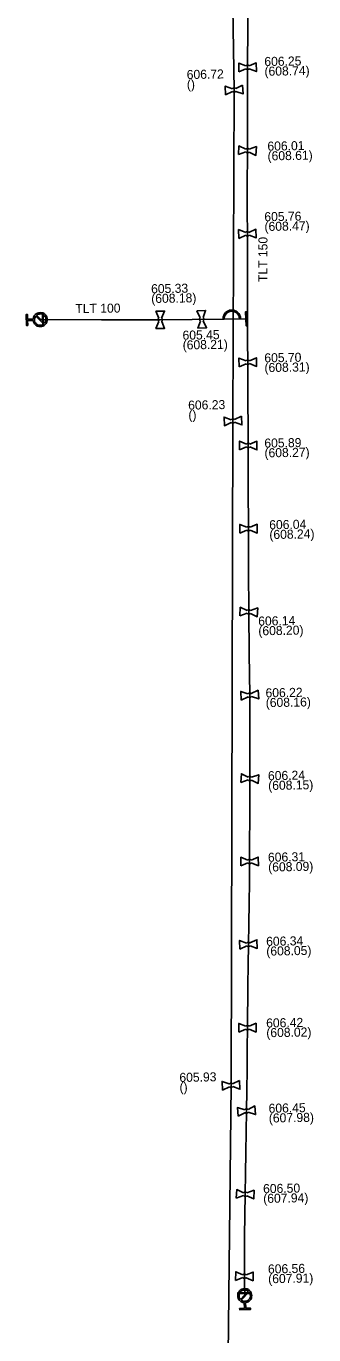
# Model space of a CAD drawing. Extents: x -643842 to -636370, y -1119190 to -1110210.
# Drawn here: x -640525.1 to -640483.8, y -1115566.2 to -1115378.3 of the extents above; entities that cross this region are included whole.
import ezdxf

# ---------------------------------------------------------------- set-up
doc = ezdxf.new("R2010")
doc.units = 0
for name, color, linetype in [('9', 7, 'Continuous'), ('Default', 7, 'Continuous'), ('Level 16', 7, 'Continuous'), ('Level 20', 7, 'Continuous'), ('Level 21', 7, 'Continuous'), ('Level 27', 7, 'Continuous'), ('Level 28', 7, 'Continuous'), ('Level 33', 7, 'Continuous')]:
    doc.layers.add(name, color=color, linetype=linetype)

msp = doc.modelspace()

# ---------------------------------------------------------------- linework, layer by layer
at = {"layer": '9'}
for points in [[(-640496.7, -1115420.35), (-640496.85, -1115420.35)], [(-640494.35, -1115420.35), (-640494.51, -1115420.35)]]:
    msp.add_lwpolyline(points, dxfattribs=at)
at = {"layer": 'Default'}
for points in [[(-640493.57, -1115384.05), (-640493.54, -1115384.01), (-640493.49, -1115383.98), (-640493.42, -1115383.94), (-640493.33, -1115383.94), (-640493.25, -1115383.94), (-640493.18, -1115383.98), (-640493.13, -1115384), (-640493.1, -1115384.04)], [(-640493.09, -1115384.45), (-640493.12, -1115384.49), (-640493.17, -1115384.52), (-640493.24, -1115384.56), (-640493.33, -1115384.56), (-640493.41, -1115384.56), (-640493.48, -1115384.52), (-640493.53, -1115384.5), (-640493.57, -1115384.46)], [(-640495.52, -1115387.32), (-640495.49, -1115387.28), (-640495.44, -1115387.25), (-640495.37, -1115387.2), (-640495.29, -1115387.2), (-640495.2, -1115387.19), (-640495.13, -1115387.23), (-640495.08, -1115387.26), (-640495.04, -1115387.29)], [(-640495.02, -1115387.7), (-640495.05, -1115387.74), (-640495.1, -1115387.77), (-640495.17, -1115387.82), (-640495.25, -1115387.82), (-640495.34, -1115387.83), (-640495.41, -1115387.79), (-640495.46, -1115387.76), (-640495.5, -1115387.73)], [(-640493.12, -1115396.42), (-640493.16, -1115396.46), (-640493.21, -1115396.49), (-640493.28, -1115396.53), (-640493.36, -1115396.52), (-640493.45, -1115396.52), (-640493.52, -1115396.47), (-640493.56, -1115396.44), (-640493.6, -1115396.4)], [(-640493.58, -1115395.99), (-640493.54, -1115395.96), (-640493.49, -1115395.93), (-640493.42, -1115395.89), (-640493.34, -1115395.9), (-640493.25, -1115395.9), (-640493.18, -1115395.95), (-640493.14, -1115395.98), (-640493.1, -1115396.02)], [(-640493.61, -1115407.95), (-640493.58, -1115407.91), (-640493.53, -1115407.88), (-640493.46, -1115407.84), (-640493.38, -1115407.84), (-640493.29, -1115407.84), (-640493.22, -1115407.88), (-640493.17, -1115407.9), (-640493.14, -1115407.94)], [(-640493.13, -1115408.35), (-640493.16, -1115408.39), (-640493.21, -1115408.42), (-640493.28, -1115408.46), (-640493.36, -1115408.46), (-640493.45, -1115408.46), (-640493.52, -1115408.42), (-640493.57, -1115408.4), (-640493.6, -1115408.36)], [(-640524.09, -1115420.4), (-640524.07, -1115420.04), (-640523.81, -1115419.77), (-640523.52, -1115419.48), (-640523.11, -1115419.47), (-640522.69, -1115419.46), (-640522.4, -1115419.75), (-640522.1, -1115420.04), (-640522.09, -1115420.45), (-640522.08, -1115420.87), (-640522.37, -1115421.16), (-640522.66, -1115421.46), (-640523.07, -1115421.47), (-640523.49, -1115421.48), (-640523.78, -1115421.19), (-640524.05, -1115420.94), (-640524.08, -1115420.58)], [(-640523.74, -1115419.97), (-640523.91, -1115420.19), (-640523.9, -1115420.49), (-640523.9, -1115420.83), (-640523.66, -1115421.06), (-640523.41, -1115421.29), (-640523.08, -1115421.28), (-640522.78, -1115421.28), (-640522.57, -1115421.1)], [(-640522.44, -1115420.97), (-640522.27, -1115420.75), (-640522.28, -1115420.46), (-640522.29, -1115420.12), (-640522.53, -1115419.89), (-640522.77, -1115419.65), (-640523.11, -1115419.66), (-640523.4, -1115419.67), (-640523.61, -1115419.84)], [(-640496.85, -1115420.35), (-640496.85, -1115420.03), (-640496.69, -1115419.73), (-640496.52, -1115419.43), (-640496.22, -1115419.26), (-640495.92, -1115419.1), (-640495.6, -1115419.1), (-640495.29, -1115419.1), (-640494.99, -1115419.26), (-640494.69, -1115419.43), (-640494.52, -1115419.73), (-640494.35, -1115420.03), (-640494.35, -1115420.35)], [(-640494.51, -1115420.35), (-640494.51, -1115420.07), (-640494.66, -1115419.8), (-640494.81, -1115419.54), (-640495.07, -1115419.4), (-640495.33, -1115419.26), (-640495.6, -1115419.26), (-640495.88, -1115419.26), (-640496.14, -1115419.4), (-640496.4, -1115419.54), (-640496.55, -1115419.8), (-640496.7, -1115420.07), (-640496.7, -1115420.35)], [(-640506.07, -1115420.73), (-640506.11, -1115420.69), (-640506.14, -1115420.65), (-640506.18, -1115420.57), (-640506.18, -1115420.49), (-640506.18, -1115420.41), (-640506.14, -1115420.33), (-640506.12, -1115420.29), (-640506.08, -1115420.25)], [(-640505.67, -1115420.25), (-640505.63, -1115420.28), (-640505.6, -1115420.33), (-640505.56, -1115420.41), (-640505.56, -1115420.49), (-640505.56, -1115420.57), (-640505.6, -1115420.64), (-640505.62, -1115420.69), (-640505.66, -1115420.73)], [(-640500.11, -1115420.67), (-640500.15, -1115420.64), (-640500.18, -1115420.59), (-640500.23, -1115420.52), (-640500.23, -1115420.44), (-640500.24, -1115420.36), (-640500.2, -1115420.28), (-640500.18, -1115420.23), (-640500.14, -1115420.19)], [(-640499.73, -1115420.17), (-640499.69, -1115420.2), (-640499.66, -1115420.25), (-640499.61, -1115420.32), (-640499.61, -1115420.4), (-640499.6, -1115420.48), (-640499.64, -1115420.56), (-640499.66, -1115420.61), (-640499.7, -1115420.64)], [(-640493.55, -1115426.39), (-640493.52, -1115426.35), (-640493.47, -1115426.32), (-640493.4, -1115426.28), (-640493.32, -1115426.28), (-640493.24, -1115426.28), (-640493.16, -1115426.32), (-640493.11, -1115426.34), (-640493.08, -1115426.38)], [(-640493.07, -1115426.79), (-640493.1, -1115426.83), (-640493.15, -1115426.86), (-640493.22, -1115426.9), (-640493.3, -1115426.9), (-640493.38, -1115426.9), (-640493.46, -1115426.86), (-640493.51, -1115426.84), (-640493.54, -1115426.8)], [(-640495.69, -1115434.83), (-640495.66, -1115434.79), (-640495.61, -1115434.76), (-640495.54, -1115434.71), (-640495.46, -1115434.71), (-640495.37, -1115434.7), (-640495.3, -1115434.74), (-640495.25, -1115434.77), (-640495.21, -1115434.8)], [(-640495.19, -1115435.21), (-640495.22, -1115435.25), (-640495.27, -1115435.28), (-640495.34, -1115435.33), (-640495.42, -1115435.33), (-640495.51, -1115435.34), (-640495.58, -1115435.3), (-640495.63, -1115435.27), (-640495.67, -1115435.24)], [(-640493.48, -1115438.33), (-640493.44, -1115438.3), (-640493.4, -1115438.27), (-640493.32, -1115438.23), (-640493.24, -1115438.23), (-640493.16, -1115438.23), (-640493.08, -1115438.27), (-640493.04, -1115438.3), (-640493, -1115438.34)], [(-640493, -1115438.74), (-640493.04, -1115438.78), (-640493.09, -1115438.81), (-640493.16, -1115438.85), (-640493.24, -1115438.85), (-640493.32, -1115438.85), (-640493.4, -1115438.81), (-640493.44, -1115438.78), (-640493.48, -1115438.74)], [(-640493.45, -1115450.28), (-640493.41, -1115450.24), (-640493.37, -1115450.21), (-640493.29, -1115450.17), (-640493.21, -1115450.17), (-640493.13, -1115450.17), (-640493.06, -1115450.21), (-640493.01, -1115450.24), (-640492.97, -1115450.28)], [(-640492.97, -1115450.68), (-640493.01, -1115450.72), (-640493.05, -1115450.75), (-640493.13, -1115450.79), (-640493.21, -1115450.79), (-640493.29, -1115450.79), (-640493.37, -1115450.75), (-640493.41, -1115450.72), (-640493.45, -1115450.68)], [(-640492.93, -1115462.64), (-640492.97, -1115462.68), (-640493.02, -1115462.71), (-640493.09, -1115462.75), (-640493.17, -1115462.74), (-640493.26, -1115462.74), (-640493.33, -1115462.69), (-640493.37, -1115462.66), (-640493.41, -1115462.62)], [(-640493.39, -1115462.21), (-640493.35, -1115462.18), (-640493.31, -1115462.15), (-640493.23, -1115462.11), (-640493.15, -1115462.12), (-640493.06, -1115462.12), (-640492.99, -1115462.17), (-640492.95, -1115462.2), (-640492.91, -1115462.24)], [(-640493.28, -1115474.19), (-640493.25, -1115474.15), (-640493.2, -1115474.12), (-640493.13, -1115474.07), (-640493.05, -1115474.07), (-640492.97, -1115474.06), (-640492.89, -1115474.1), (-640492.84, -1115474.12), (-640492.81, -1115474.16)], [(-640492.78, -1115474.57), (-640492.81, -1115474.61), (-640492.86, -1115474.64), (-640492.93, -1115474.69), (-640493.01, -1115474.69), (-640493.09, -1115474.7), (-640493.17, -1115474.66), (-640493.22, -1115474.64), (-640493.25, -1115474.6)], [(-640492.79, -1115486.57), (-640492.83, -1115486.6), (-640492.88, -1115486.63), (-640492.96, -1115486.67), (-640493.04, -1115486.66), (-640493.12, -1115486.66), (-640493.19, -1115486.61), (-640493.24, -1115486.58), (-640493.27, -1115486.54)], [(-640493.25, -1115486.13), (-640493.21, -1115486.1), (-640493.16, -1115486.07), (-640493.08, -1115486.03), (-640493, -1115486.04), (-640492.92, -1115486.04), (-640492.85, -1115486.09), (-640492.8, -1115486.12), (-640492.77, -1115486.16)], [(-640493.29, -1115498.05), (-640493.26, -1115498.01), (-640493.21, -1115497.98), (-640493.14, -1115497.94), (-640493.05, -1115497.94), (-640492.97, -1115497.94), (-640492.9, -1115497.98), (-640492.85, -1115498), (-640492.82, -1115498.04)], [(-640492.81, -1115498.45), (-640492.84, -1115498.49), (-640492.89, -1115498.52), (-640492.96, -1115498.56), (-640493.05, -1115498.56), (-640493.13, -1115498.56), (-640493.2, -1115498.52), (-640493.25, -1115498.5), (-640493.29, -1115498.46)], [(-640493.47, -1115509.96), (-640493.43, -1115509.92), (-640493.39, -1115509.9), (-640493.31, -1115509.85), (-640493.23, -1115509.85), (-640493.15, -1115509.84), (-640493.08, -1115509.88), (-640493.03, -1115509.91), (-640492.99, -1115509.95)], [(-640492.98, -1115510.35), (-640493.01, -1115510.4), (-640493.05, -1115510.42), (-640493.13, -1115510.47), (-640493.21, -1115510.47), (-640493.29, -1115510.48), (-640493.37, -1115510.44), (-640493.41, -1115510.41), (-640493.45, -1115510.37)], [(-640493.6, -1115521.91), (-640493.57, -1115521.87), (-640493.52, -1115521.84), (-640493.44, -1115521.8), (-640493.36, -1115521.8), (-640493.28, -1115521.8), (-640493.21, -1115521.84), (-640493.16, -1115521.86), (-640493.12, -1115521.9)], [(-640493.12, -1115522.31), (-640493.16, -1115522.35), (-640493.2, -1115522.38), (-640493.28, -1115522.42), (-640493.36, -1115522.42), (-640493.44, -1115522.42), (-640493.52, -1115522.38), (-640493.56, -1115522.36), (-640493.6, -1115522.32)], [(-640495.96, -1115530.19), (-640495.93, -1115530.15), (-640495.88, -1115530.12), (-640495.81, -1115530.07), (-640495.73, -1115530.07), (-640495.64, -1115530.06), (-640495.57, -1115530.1), (-640495.52, -1115530.13), (-640495.48, -1115530.16)], [(-640495.46, -1115530.57), (-640495.49, -1115530.61), (-640495.54, -1115530.64), (-640495.61, -1115530.69), (-640495.69, -1115530.69), (-640495.78, -1115530.7), (-640495.85, -1115530.66), (-640495.9, -1115530.63), (-640495.94, -1115530.6)], [(-640493.75, -1115533.9), (-640493.72, -1115533.86), (-640493.67, -1115533.83), (-640493.6, -1115533.78), (-640493.52, -1115533.77), (-640493.44, -1115533.76), (-640493.36, -1115533.79), (-640493.31, -1115533.82), (-640493.27, -1115533.85)], [(-640493.23, -1115534.26), (-640493.26, -1115534.3), (-640493.31, -1115534.33), (-640493.38, -1115534.38), (-640493.46, -1115534.39), (-640493.54, -1115534.4), (-640493.62, -1115534.36), (-640493.67, -1115534.34), (-640493.71, -1115534.31)], [(-640493.91, -1115545.8), (-640493.87, -1115545.77), (-640493.83, -1115545.74), (-640493.75, -1115545.7), (-640493.67, -1115545.71), (-640493.58, -1115545.71), (-640493.51, -1115545.76), (-640493.47, -1115545.78), (-640493.43, -1115545.83)], [(-640493.45, -1115546.23), (-640493.49, -1115546.27), (-640493.54, -1115546.3), (-640493.61, -1115546.34), (-640493.69, -1115546.33), (-640493.78, -1115546.33), (-640493.85, -1115546.28), (-640493.89, -1115546.26), (-640493.93, -1115546.21)], [(-640493.56, -1115558), (-640493.59, -1115558.04), (-640493.64, -1115558.06), (-640493.71, -1115558.1), (-640493.8, -1115558.1), (-640493.88, -1115558.1), (-640493.95, -1115558.06), (-640494, -1115558.03), (-640494.03, -1115557.99)], [(-640494.02, -1115557.58), (-640493.99, -1115557.54), (-640493.94, -1115557.52), (-640493.87, -1115557.48), (-640493.78, -1115557.48), (-640493.7, -1115557.48), (-640493.63, -1115557.52), (-640493.58, -1115557.55), (-640493.55, -1115557.59)], [(-640493.81, -1115561.58), (-640494.17, -1115561.56), (-640494.44, -1115561.31), (-640494.74, -1115561.02), (-640494.75, -1115560.61), (-640494.76, -1115560.19), (-640494.48, -1115559.89), (-640494.19, -1115559.59), (-640493.78, -1115559.58), (-640493.36, -1115559.57), (-640493.06, -1115559.85), (-640492.76, -1115560.14), (-640492.75, -1115560.55), (-640492.74, -1115560.97), (-640493.02, -1115561.27), (-640493.27, -1115561.54), (-640493.63, -1115561.57)], [(-640493.26, -1115559.93), (-640493.48, -1115559.76), (-640493.77, -1115559.77), (-640494.11, -1115559.78), (-640494.34, -1115560.02), (-640494.57, -1115560.27), (-640494.56, -1115560.61), (-640494.55, -1115560.89), (-640494.37, -1115561.11)], [(-640494.24, -1115561.23), (-640494.02, -1115561.4), (-640493.72, -1115561.39), (-640493.39, -1115561.38), (-640493.16, -1115561.14), (-640492.93, -1115560.9), (-640492.94, -1115560.56), (-640492.94, -1115560.27), (-640493.13, -1115560.05)]]:
    msp.add_open_spline(points, degree=3, dxfattribs=at)
at = {"layer": 'Level 16'}
for points in [[(-640522.67, -1115419.72), (-640522.62, -1115421.22), (-640522.71, -1115421.22), (-640522.76, -1115419.72), (-640522.67, -1115419.72)], [(-640493.5, -1115419.35), (-640493.42, -1115421.35), (-640493.54, -1115421.35), (-640493.62, -1115419.35), (-640493.5, -1115419.35)], [(-640494.49, -1115560.19), (-640492.99, -1115560.17), (-640492.99, -1115560.27), (-640494.49, -1115560.29), (-640494.49, -1115560.19)]]:
    msp.add_lwpolyline(points, dxfattribs=at)
at = {"layer": 'Level 21'}
for points in [[(-640496.45, -1115599.22), (-640495.71, -1115530.38), (-640495.44, -1115435.02), (-640495.27, -1115387.51), (-640496.24, -1115328.66), (-640496.1, -1115321.04), (-640496.38, -1115277.05), (-640496.25, -1115224.64), (-640497.04, -1115169.68), (-640497.03, -1115117.29), (-640497.07, -1115108.05), (-640496.9, -1115096.11)], [(-640493.19, -1115367.24), (-640493.22, -1115369.77), (-640493.26, -1115372.29), (-640493.28, -1115375.27), (-640493.3, -1115378.26), (-640493.33, -1115384.25), (-640493.34, -1115390.24), (-640493.35, -1115396.21), (-640493.42, -1115401.65), (-640493.4, -1115404.9), (-640493.37, -1115408.15), (-640493.34, -1115414.13), (-640493.35, -1115417.24), (-640493.36, -1115420.34)], [(-640493.36, -1115420.34), (-640493.52, -1115420.35), (-640496.72, -1115420.39), (-640505.87, -1115420.49), (-640514.28, -1115420.48), (-640522.69, -1115420.47), (-640523.09, -1115420.47)], [(-640493.36, -1115420.34), (-640493.33, -1115423.47), (-640493.31, -1115426.59), (-640493.28, -1115432.56), (-640493.26, -1115435.55), (-640493.24, -1115438.54), (-640493.23, -1115444.51), (-640493.21, -1115450.48), (-640493.2, -1115456.46), (-640493.16, -1115462.43), (-640493.11, -1115468.39), (-640493.03, -1115474.38), (-640493.02, -1115477.36), (-640493.01, -1115480.35), (-640493.02, -1115486.35), (-640493.03, -1115492.31), (-640493.04, -1115495.28), (-640493.08, -1115501.22), (-640493.12, -1115504.19), (-640493.17, -1115507.18), (-640493.22, -1115510.16), (-640493.25, -1115513.11), (-640493.28, -1115516.07), (-640493.36, -1115522.11), (-640493.39, -1115525.1), (-640493.41, -1115528.1), (-640493.45, -1115531.09), (-640493.49, -1115534.08), (-640493.54, -1115537.06), (-640493.58, -1115540.05), (-640493.63, -1115543.03), (-640493.68, -1115546.02), (-640493.72, -1115549.02), (-640493.76, -1115552.03), (-640493.78, -1115554.91), (-640493.79, -1115557.79), (-640493.77, -1115559.01), (-640493.74, -1115560.23), (-640493.75, -1115560.58)]]:
    msp.add_lwpolyline(points, dxfattribs=at)
at = {"layer": 'Level 28'}
for points in [[(-640494.57, -1115384.89), (-640494.59, -1115383.64), (-640493.57, -1115384.05)], [(-640493.1, -1115384.04), (-640492.09, -1115383.61), (-640492.07, -1115384.86), (-640493.09, -1115384.45)], [(-640493.57, -1115384.46), (-640494.57, -1115384.89)], [(-640495.5, -1115387.73), (-640496.49, -1115388.2), (-640496.55, -1115386.95), (-640495.52, -1115387.32)], [(-640495.04, -1115387.29), (-640494.05, -1115386.82)], [(-640494.05, -1115386.82), (-640493.99, -1115388.07), (-640495.02, -1115387.7)], [(-640494.63, -1115396.78), (-640494.57, -1115395.53), (-640493.58, -1115395.99)], [(-640493.6, -1115396.4), (-640494.63, -1115396.78)], [(-640493.1, -1115396.02), (-640492.07, -1115395.64), (-640492.13, -1115396.89), (-640493.12, -1115396.42)], [(-640494.61, -1115408.8), (-640494.63, -1115407.55), (-640493.61, -1115407.95)], [(-640493.6, -1115408.36), (-640494.61, -1115408.8)], [(-640493.14, -1115407.94), (-640492.13, -1115407.5), (-640492.11, -1115408.75), (-640493.13, -1115408.35)], [(-640506.5, -1115419.24), (-640505.25, -1115419.24), (-640505.67, -1115420.25)], [(-640506.08, -1115420.25), (-640506.5, -1115419.24)], [(-640500.62, -1115419.21), (-640499.37, -1115419.14), (-640499.73, -1115420.17)], [(-640500.14, -1115420.19), (-640500.62, -1115419.21)], [(-640505.66, -1115420.73), (-640505.24, -1115421.74), (-640506.49, -1115421.74), (-640506.07, -1115420.73)], [(-640499.7, -1115420.64), (-640499.22, -1115421.63), (-640500.47, -1115421.7), (-640500.11, -1115420.67)], [(-640494.54, -1115427.25), (-640494.58, -1115426), (-640493.55, -1115426.39)], [(-640493.54, -1115426.8), (-640494.54, -1115427.25)], [(-640493.08, -1115426.38), (-640492.08, -1115425.93), (-640492.04, -1115427.18), (-640493.07, -1115426.79)], [(-640495.67, -1115435.24), (-640496.66, -1115435.71), (-640496.72, -1115434.46), (-640495.69, -1115434.83)], [(-640495.21, -1115434.8), (-640494.22, -1115434.33)], [(-640494.22, -1115434.33), (-640494.16, -1115435.58), (-640495.19, -1115435.21)], [(-640494.49, -1115439.16), (-640494.49, -1115437.91), (-640493.48, -1115438.33)], [(-640493.48, -1115438.74), (-640494.49, -1115439.16)], [(-640493, -1115438.34), (-640491.99, -1115437.92), (-640491.99, -1115439.17), (-640493, -1115438.74)], [(-640494.46, -1115451.11), (-640494.46, -1115449.86), (-640493.45, -1115450.28)], [(-640492.97, -1115450.28), (-640491.96, -1115449.85), (-640491.96, -1115451.1), (-640492.97, -1115450.68)], [(-640493.45, -1115450.68), (-640494.46, -1115451.11)], [(-640494.44, -1115463), (-640494.38, -1115461.75), (-640493.39, -1115462.21)], [(-640493.41, -1115462.62), (-640494.44, -1115463)], [(-640492.91, -1115462.24), (-640491.88, -1115461.86), (-640491.94, -1115463.11), (-640492.93, -1115462.64)], [(-640494.24, -1115475.08), (-640494.32, -1115473.84), (-640493.28, -1115474.19)], [(-640492.81, -1115474.16), (-640491.82, -1115473.68), (-640491.74, -1115474.92), (-640492.78, -1115474.57)], [(-640493.25, -1115474.6), (-640494.24, -1115475.08)], [(-640494.3, -1115486.91), (-640494.23, -1115485.66), (-640493.25, -1115486.13)], [(-640493.27, -1115486.54), (-640494.3, -1115486.91)], [(-640492.77, -1115486.16), (-640491.74, -1115485.79), (-640491.81, -1115487.04), (-640492.79, -1115486.57)], [(-640494.29, -1115498.89), (-640494.31, -1115497.64), (-640493.29, -1115498.05)], [(-640493.29, -1115498.46), (-640494.29, -1115498.89)], [(-640492.82, -1115498.04), (-640491.81, -1115497.61), (-640491.79, -1115498.86), (-640492.81, -1115498.45)], [(-640494.44, -1115510.83), (-640494.49, -1115509.59), (-640493.47, -1115509.96)], [(-640492.99, -1115509.95), (-640492, -1115509.49), (-640491.95, -1115510.73), (-640492.98, -1115510.35)], [(-640493.45, -1115510.37), (-640494.44, -1115510.83)], [(-640494.61, -1115522.74), (-640494.61, -1115521.49), (-640493.6, -1115521.91)], [(-640493.6, -1115522.32), (-640494.61, -1115522.74)], [(-640493.12, -1115521.9), (-640492.11, -1115521.48), (-640492.11, -1115522.73), (-640493.12, -1115522.31)], [(-640495.94, -1115530.6), (-640496.93, -1115531.07), (-640496.99, -1115529.82), (-640495.96, -1115530.19)], [(-640495.48, -1115530.16), (-640494.49, -1115529.69)], [(-640494.49, -1115529.69), (-640494.43, -1115530.94), (-640495.46, -1115530.57)], [(-640494.67, -1115534.83), (-640494.8, -1115533.58), (-640493.75, -1115533.9)], [(-640493.71, -1115534.31), (-640494.67, -1115534.83)], [(-640493.27, -1115533.85), (-640492.31, -1115533.33), (-640492.18, -1115534.58), (-640493.23, -1115534.26)], [(-640494.96, -1115546.59), (-640494.9, -1115545.34), (-640493.91, -1115545.8)], [(-640493.43, -1115545.83), (-640492.4, -1115545.45), (-640492.46, -1115546.7), (-640493.45, -1115546.23)], [(-640493.93, -1115546.21), (-640494.96, -1115546.59)], [(-640495.05, -1115558.39), (-640495.03, -1115557.14), (-640494.02, -1115557.58)], [(-640494.03, -1115557.99), (-640495.05, -1115558.39)], [(-640493.55, -1115557.59), (-640492.53, -1115557.19), (-640492.55, -1115558.44), (-640493.56, -1115558)]]:
    msp.add_lwpolyline(points, dxfattribs=at)
at = {"layer": 'Level 33'}
for points in [[(-640524.08, -1115420.58), (-640524.9, -1115420.6), (-640524.89, -1115421.29), (-640525.07, -1115421.29), (-640525.1, -1115419.73), (-640524.92, -1115419.72), (-640524.91, -1115420.41), (-640524.09, -1115420.4)], [(-640522.57, -1115421.1), (-640523.74, -1115419.97)], [(-640523.61, -1115419.84), (-640522.44, -1115420.97)], [(-640494.37, -1115561.11), (-640493.26, -1115559.93)], [(-640493.13, -1115560.05), (-640494.24, -1115561.23)], [(-640493.63, -1115561.57), (-640493.61, -1115562.39), (-640492.92, -1115562.37), (-640492.91, -1115562.56), (-640494.47, -1115562.6), (-640494.48, -1115562.42), (-640493.79, -1115562.4), (-640493.81, -1115561.58)]]:
    msp.add_lwpolyline(points, dxfattribs=at)

# ---------------------------------------------------------------- texts
at = {"layer": 'Level 20'}
for s, rotation, p in [('TLT 150', 89.8155, (-640490.5, -1115415.07)), ('TLT 100', 0.6575, (-640518.04, -1115419.53))]:
    msp.add_text(s, height=1.3, rotation=rotation, dxfattribs=at).set_placement(p)
at = {"layer": 'Level 27'}
for s, p in [('606.25', (-640490.92, -1115384.07)), ('(608.74)', (-640490.9, -1115385.47)), ('606.72', (-640502.06, -1115385.94)), ('()', (-640502.04, -1115387.34)), ('606.01', (-640490.48, -1115396.22)), ('(608.61)', (-640490.46, -1115397.62)), ('605.76', (-640490.92, -1115406.35)), ('(608.47)', (-640490.9, -1115407.75)), ('605.33', (-640507.17, -1115416.69)), ('(608.18)', (-640507.15, -1115418.09)), ('605.45', (-640502.66, -1115423.36)), ('(608.21)', (-640502.64, -1115424.76)), ('605.70', (-640490.92, -1115426.61)), ('(608.31)', (-640490.9, -1115428.01)), ('606.23', (-640501.85, -1115433.4)), ('()', (-640501.82, -1115434.8)), ('605.89', (-640490.92, -1115438.85)), ('(608.27)', (-640490.9, -1115440.25)), ('606.04', (-640490.22, -1115450.57)), ('(608.24)', (-640490.2, -1115451.97)), ('606.14', (-640491.8, -1115464.4)), ('(608.20)', (-640491.78, -1115465.79)), ('606.22', (-640490.75, -1115474.7)), ('(608.16)', (-640490.72, -1115476.1)), ('606.24', (-640490.4, -1115486.59)), ('(608.15)', (-640490.37, -1115487.99)), ('606.31', (-640490.4, -1115498.3)), ('(608.09)', (-640490.37, -1115499.7)), ('606.34', (-640490.66, -1115510.37)), ('(608.05)', (-640490.64, -1115511.77)), ('606.42', (-640490.66, -1115522.09)), ('(608.02)', (-640490.64, -1115523.48)), ('605.93', (-640503.11, -1115529.9)), ('()', (-640503.09, -1115531.3)), ('606.45', (-640490.31, -1115534.33)), ('(607.98)', (-640490.28, -1115535.73)), ('606.50', (-640491.1, -1115545.87)), ('(607.94)', (-640491.08, -1115547.27)), ('606.56', (-640490.4, -1115557.4)), ('(607.91)', (-640490.37, -1115558.8))]:
    msp.add_text(s, height=1.3, rotation=1, dxfattribs=at).set_placement(p)

doc.saveas('drawing.dxf')
